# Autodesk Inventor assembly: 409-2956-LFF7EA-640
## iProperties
Created: 2010-06
Part Number: 409-2956-LFF7EA-640
Document SubType Name: Assembly
Designer: S. Boerckel
Mass: 36670.2 g
Surface Area: 22334.2 cm^2
Volume: 4665.12 cm^3
Density: 7.86051 g/cm^3
Description: PRESSURE DIFFERENTIAL MOUNT
User Status: ASSEMBLY
Material: ASSEMBLY
SMR: =<Material>
Length: 42.875 in
Wide: 23.000 in
Thickness: 10.750 in
Subject: DEMIN WATER FORWARDING PUMP SKID-7EA
Author: S. Boerckel
Revision Number: 0
